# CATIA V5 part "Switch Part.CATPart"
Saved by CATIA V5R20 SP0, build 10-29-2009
Part number: Part2
Bounding box of the stored display mesh (mm): x -10 to 73.145, y -224.581 to 224.581, z -167.5 to 132.5
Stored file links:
  C:\Users\HP\Downloads\Catia Project\Catia Project\Switch Part.CATPart
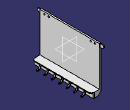
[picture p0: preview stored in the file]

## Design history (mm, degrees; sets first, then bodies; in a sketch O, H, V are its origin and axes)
Body1 (main body)
  Sketch1 on yz-plane, origin (0, 0, 0), H (0, 1, 0), V (0, 0, 1)
    line L1 (200, 132.5) -> (200, -132.5)
    line L2 (200, -132.5) -> (-200, -132.5)
    line L3 (-200, -132.5) -> (-200, 132.5)
    line L4 (-200, 132.5) -> (200, 132.5)
  Pad1: profile Sketch1, direction (-1, 0, 0), length 10
  Sketch2 on face of Pad1 from Sketch1.L1, origin (0, 200, 0), H (-1, 0, 0), V (0, 0, 1)
    projected line E1 (0, -132.5) -> (10, -132.5) from edge [face of Pad1 from Sketch1.L2 | face of Pad1 from Sketch1.L1]
    line L1 (10, -132.5) -> (10, -167.5)
    line L2 (10, -167.5) -> (-40, -167.5)
    line L3 (-40, -167.5) -> (-40, -132.5)
    line L4 (-40, -132.5) -> (0, -132.5)
    length L1 = 35
    distance L3 L1 = 50
  Pad2: profile Sketch2, direction (0, -1, 0), up to face of Pad1 from Sketch1.L3
  Chamfer1: length 20, angle 45, on edge [face of Pad2 from Sketch2.L2 | face of Pad1]
  Sketch3 on face of Pad2 from Sketch2.L4, origin (0, 0, -132.5), H (1, 0, 0), V (0, 1, 0)
    projected line E1 (40, 200) -> (40, -200) from edge [face of Pad2 from Sketch2.L4 | face of Pad2 from Sketch2.L3]
    line L1 (40, -200) -> (53.5091, -200)
    line L2 (53.5091, -200) -> (53.5091, 200)
    line L3 (53.5091, 200) -> (40, 200)
  Pad3: profile Sketch3, direction (0, 0, -1), length 5
  Fillet1: radius 20, on edge [face of Pad3 from Sketch3.L2 | face of Pad3]
  Fillet2: radius 20, on edge [face of Pad3 | face of Pad3 from Sketch3.L2]
  Sketch4 on zx-plane, origin (0, 0, 0), H (-1, 0, 0), V (0, 0, 1)
    line L1 (-49.8867, -135.03) -> (-43.2325, -135.03)
    line L2 (-49.8867, -135.03) -> (-49.8867, -149.3617)
    line L3 (-49.8867, -149.3617) -> (-58.031, -161.7828)
    line L4 (-58.031, -161.7828) -> (-73.1455, -161.7828)
    line L5 (-43.2325, -135.03) -> (-43.2325, -149.3617)
    line L6 (-43.2325, -149.3617) -> (-56.5492, -166.5146)
    line L7 (-56.5492, -166.5146) -> (-73.1455, -166.5146)
    line L8 (-73.1455, -161.7828) -> (-73.1455, -166.5146)
  Pad4: profile Sketch4, direction (0, 1, 0), length 4, opposite side length 4
  Fillet3: radius 3, on edge [face of Pad4 from Sketch4.L8 | end face of Pad4]; edge [start face of Pad4 | face of Pad4 from Sketch4.L8]
  Sketch5 on face of Pad4 from Sketch4.L4, origin (0, 0, -161.7828), H (1, 0, 0), V (0, 1, 0)
    circle A1 centre (69.2041, 0) radius 2.0849
  Pocket1: profile Sketch5, direction (0, 0, -1), length 10
  RectPattern1: of Pad4, Fillet3, Pocket1, direction 1 instances 4, spacing 50, along edge [face of Pad2 from Sketch2.L3 | face of Pad2 from Sketch2.L2]
  RectPattern2: of Pad4, Fillet3, Pocket1, direction 1 instances 4, spacing 50, along edge [face of Pad2 from Sketch2.L3 | face of Pad2 from Sketch2.L2] reversed
  Sketch6 on face of Pad1, origin (-10, 0, 0), H (0, -1, 0), V (0, 0, 1)
    point P1 (0, 119.5559)
    line L1 (209.9466, 108.4807) -> (-209.9466, 108.4807)
    line L2 (-209.9466, 130.6311) -> (209.9466, 130.6311)
    point P4 (-209.9466, 108.4807)
    point P5 (-209.9466, 130.6311)
    line L3 (209.9466, 108.4807) -> (223.5311, 115.4999)
    line L4 (209.9466, 130.6311) -> (223.5311, 126.0165)
    arc A1 centre (212.4366, 120.7582) radius 12.2775 from (223.5311, 115.4999) to (223.5311, 126.0165) ccw
    point P9 (-209.9466, 130.6311)
    point P10 (-209.9466, 108.4807)
    line L5 (-209.9466, 108.4807) -> (-223.5311, 115.4999)
    line L6 (-209.9466, 130.6311) -> (-223.5311, 126.0165)
    arc A2 centre (-212.4366, 120.7582) radius 12.2775 from (-223.5311, 115.4999) to (-223.5311, 126.0165) cw
    coincidence: P4 P10, P5 P9
  Pad5: profile Sketch6, direction (1, 0, 0), length 5
  Sketch7 on face of Pad5, origin (-10, 0, 0), H (0, -1, 0), V (0, 0, 1)
    circle A1 centre (170.0815, 118.2431) radius 5.1392
    circle A2 centre (141.7235, 118.2431) radius 5.1392
    circle A3 centre (-170.0815, 118.2431) radius 5.1392
    circle A4 centre (-141.7235, 118.2431) radius 5.1392
    circle A5 centre (170.0815, -147.4514) radius 5.1392
    circle A6 centre (141.7235, -147.4514) radius 5.1392
    circle A7 centre (-170.0815, -147.4514) radius 5.1392
    circle A8 centre (-141.7235, -147.4514) radius 5.1392
    circle A9 centre (0, -147.4514) radius 5.6707
  Pocket2: profile Sketch7, direction (1, 0, 0), length 15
